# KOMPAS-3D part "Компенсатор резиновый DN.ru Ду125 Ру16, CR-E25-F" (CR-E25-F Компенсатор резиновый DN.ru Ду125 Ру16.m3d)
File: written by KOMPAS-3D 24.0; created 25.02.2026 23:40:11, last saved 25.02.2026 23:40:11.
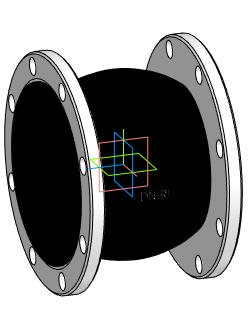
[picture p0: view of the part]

Document properties: Автор: DN.RU; Полное имя файла: D:\PROJECT CAD\DN.RU\...178(4)(ACTUALE). CR-E25-F Компенсатор резиновый DN.ru Ру10-16\DN125_PN16\CR-E25-F Компенсатор резиновый DN.ru Ду125 Ру16.m3d

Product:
- Body: Твердое тело2  | qty 1
    Масса: 19.466313
- Part/product: Компенсатор резиновый DN.ru Ду125 Ру16  | designation CR-E25-F
    Масса: 10.71
    Раздел спецификации: Прочие изделия
    Комментарий: D140-02177
    Примечание: D140-02177
    additional columns: Типовые

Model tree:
1. Твердое тело2  (labels: Твердое тело2)

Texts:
  CR-E25-F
